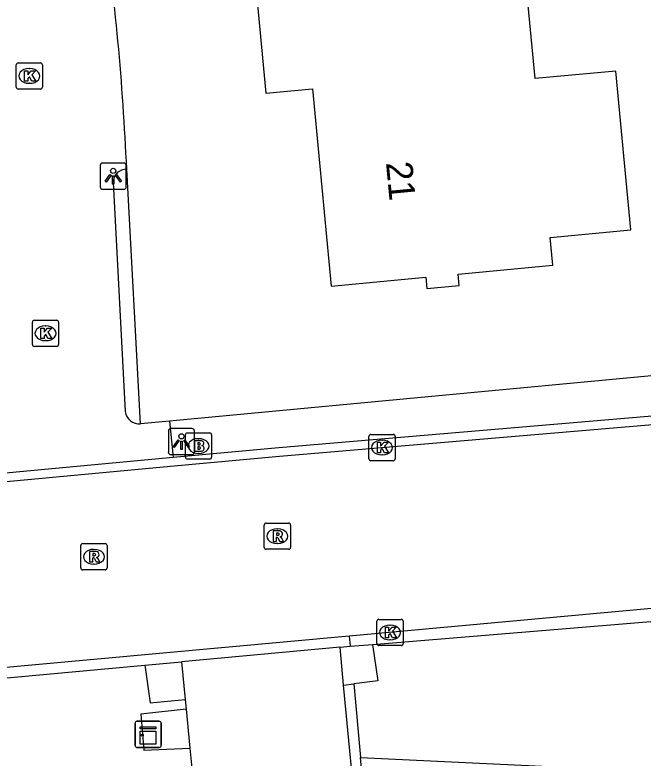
# Model space of a CAD drawing. Extents: x 162157 to 163165, y 378998 to 380775.
# Drawn here: x 162424.68 to 162448.63, y 380633 to 380661.34 of the extents above; entities that cross this region are included whole.
import ezdxf

# ---------------------------------------------------------------- set-up
doc = ezdxf.new("R2010")
doc.units = 0
for name, color, linetype in [('IMGEO_Brandkraan', 7, 'Continuous'), ('IMGEO_Groenvoorziening', 7, 'Continuous'), ('IMGEO_Kast', 7, 'Continuous'), ('IMGEO_Kolk', 7, 'Continuous'), ('IMGEO_Lichtpunt', 7, 'Continuous'), ('IMGEO_Pand', 7, 'Continuous'), ('IMGEO_Pand_nummerreeks', 7, 'Continuous'), ('IMGEO_Rijbaan_lokaal_gesloten', 7, 'Continuous'), ('IMGEO_Rijbaan_lokaal_open', 7, 'Continuous'), ('IMGEO_Rioolput', 7, 'Continuous'), ('IMGEO_Voetpad_open', 7, 'Continuous')]:
    doc.layers.add(name, color=color, linetype=linetype)

msp = doc.modelspace()

# ---------------------------------------------------------------- linework, layer by layer
at = {"layer": 'IMGEO_Brandkraan'}
for p, q in [((162431.253, 380645.401), (162432.105, 380645.401)), ((162431.178, 380644.475), (162431.178, 380645.327)), ((162431.666, 380645.181), (162431.691, 380645.181)), ((162432.179, 380645.327), (162432.179, 380644.475)), ((162431.689, 380644.621), (162431.664, 380644.621)), ((162432.105, 380644.401), (162431.253, 380644.401))]:
    msp.add_line(p, q, dxfattribs=at)
for points in [[(162431.253, 380645.401), (162432.105, 380645.401)], [(162431.178, 380644.475), (162431.178, 380645.327)], [(162431.526, 380645.101), (162431.526, 380644.701), (162431.739, 380644.701)], [(162431.757, 380645.101), (162431.526, 380645.101)], [(162432.179, 380645.327), (162432.179, 380644.475)], [(162431.705, 380645.02), (162431.651, 380645.02), (162431.651, 380644.944)], [(162431.651, 380644.944), (162431.704, 380644.944)], [(162431.713, 380644.868), (162431.651, 380644.868), (162431.651, 380644.787)], [(162431.651, 380644.787), (162431.713, 380644.787)], [(162432.105, 380644.401), (162431.253, 380644.401)]]:
    msp.add_lwpolyline(points, dxfattribs=at)
for centre, radius, start, end in [((162431.255, 380645.325), 0.0765, 91.552, 178.448), ((162431.255, 380645.325), 0.0765, 91.552, 178.448), ((162432.103, 380645.325), 0.0765, 1.552, 88.448), ((162432.103, 380645.325), 0.0765, 1.552, 88.448), ((162431.761, 380644.956), 0.145, 59.4692, 91.5367), ((162431.786, 380645.003), 0.0922, 285.5137, 58.1501), ((162431.706, 380644.982), 0.0379, 267.8285, 90.9355), ((162431.714, 380644.827), 0.0404, 269.8759, 90.5077), ((162431.791, 380644.811), 0.105, 301.3115, 78.989), ((162431.745, 380644.952), 0.251, 268.6676, 293.5347), ((162431.255, 380644.477), 0.0765, 181.552, 268.448), ((162431.255, 380644.477), 0.0765, 181.552, 268.448), ((162432.103, 380644.477), 0.0765, 271.552, 358.448), ((162432.103, 380644.477), 0.0765, 271.552, 358.448)]:
    msp.add_arc(centre, radius, start, end, dxfattribs=at)
for centre, major_axis, ratio, start_param, end_param in [((162431.665, 380644.901), (-0.387, 0.002), 0.722429, 4.712389, 7.853982), ((162431.69, 380644.901), (-0.39, 0.002), 0.717154, 1.570796, 4.712389)]:
    msp.add_ellipse(centre, major_axis=major_axis, ratio=ratio, start_param=start_param, end_param=end_param, dxfattribs=at)
at = {"layer": 'IMGEO_Groenvoorziening'}
msp.add_lwpolyline([(162437.854, 380633.025), (162463.991, 380631.774), (162466.779, 380634.155), (162485.377, 380633.853), (162489.211, 380633.646), (162492.259, 380633.107), (162495.434, 380632.111), (162498.979, 380630.341), (162500, 380629.686), (162501.777, 380628.214), (162507.464, 380626.838)], dxfattribs=at)
at = {"layer": 'IMGEO_Kast'}
for p, q in [((162429.257, 380633.482), (162429.257, 380634.323)), ((162429.257, 380634.323), (162429.257, 380633.482)), ((162429.332, 380634.407), (162430.173, 380634.407)), ((162430.173, 380634.407), (162429.332, 380634.407)), ((162430.257, 380634.332), (162430.257, 380633.491)), ((162430.257, 380633.491), (162430.257, 380634.332)), ((162430.182, 380633.407), (162429.341, 380633.407)), ((162429.341, 380633.407), (162430.182, 380633.407))]:
    msp.add_line(p, q, dxfattribs=at)
for points in [[(162429.452, 380634.197), (162430.052, 380634.197), (162430.052, 380634.112), (162429.452, 380634.112), (162429.452, 380634.197)], [(162429.452, 380634.022), (162430.052, 380634.022), (162430.052, 380633.533), (162429.452, 380633.533), (162429.452, 380634.022)]]:
    msp.add_lwpolyline(points, dxfattribs=at)
msp.add_circle((162429.536, 380633.871), 0.0377, dxfattribs=at)
for centre, start, end in [((162429.335, 380634.329), 92.4484, 184.2845), ((162429.335, 380634.329), 92.4484, 184.2845), ((162430.179, 380634.329), 2.4484, 94.2845), ((162430.179, 380634.329), 2.4484, 94.2845), ((162429.335, 380633.485), 182.4484, 274.2845), ((162429.335, 380633.485), 182.4484, 274.2845), ((162430.179, 380633.485), 272.4484, 4.2845), ((162430.179, 380633.485), 272.4484, 4.2845)]:
    msp.add_arc(centre, 0.0779, start, end, dxfattribs=at)
at = {"layer": 'IMGEO_Kolk'}
for p, q in [((162424.728, 380658.586), (162424.728, 380659.438)), ((162424.803, 380659.512), (162425.655, 380659.512)), ((162425.216, 380659.292), (162425.241, 380659.292)), ((162425.729, 380659.438), (162425.729, 380658.586)), ((162425.239, 380658.732), (162425.214, 380658.732)), ((162425.655, 380658.512), (162424.803, 380658.512)), ((162425.344, 380648.773), (162425.344, 380649.625)), ((162425.419, 380649.699), (162426.271, 380649.699)), ((162426.345, 380649.625), (162426.345, 380648.773)), ((162425.832, 380649.479), (162425.857, 380649.479)), ((162425.855, 380648.919), (162425.83, 380648.919)), ((162426.271, 380648.699), (162425.419, 380648.699)), ((162438.178, 380644.416), (162438.178, 380645.268)), ((162438.253, 380645.342), (162439.105, 380645.342)), ((162438.666, 380645.122), (162438.691, 380645.122)), ((162439.179, 380645.268), (162439.179, 380644.416)), ((162438.689, 380644.562), (162438.664, 380644.562)), ((162439.105, 380644.342), (162438.253, 380644.342)), ((162438.557, 380638.292), (162439.409, 380638.292)), ((162438.482, 380637.366), (162438.482, 380638.218)), ((162438.97, 380638.072), (162438.995, 380638.072)), ((162439.483, 380638.218), (162439.483, 380637.366)), ((162438.993, 380637.512), (162438.968, 380637.512)), ((162439.409, 380637.292), (162438.557, 380637.292))]:
    msp.add_line(p, q, dxfattribs=at)
for points in [[(162424.728, 380658.586), (162424.728, 380659.438)], [(162424.803, 380659.512), (162425.655, 380659.512)], [(162425.729, 380659.438), (162425.729, 380658.586)], [(162425.049, 380659.212), (162425.172, 380659.212), (162425.172, 380659.061), (162425.302, 380659.212), (162425.466, 380659.212), (162425.32, 380659.061), (162425.473, 380658.812), (162425.321, 380658.812), (162425.236, 380658.976), (162425.172, 380658.909), (162425.172, 380658.812), (162425.049, 380658.812), (162425.049, 380659.212)], [(162425.655, 380658.512), (162424.803, 380658.512)], [(162425.344, 380648.773), (162425.344, 380649.625)], [(162425.419, 380649.699), (162426.271, 380649.699)], [(162426.345, 380649.625), (162426.345, 380648.773)], [(162425.665, 380649.399), (162425.788, 380649.399), (162425.788, 380649.248), (162425.918, 380649.399), (162426.082, 380649.399), (162425.936, 380649.248), (162426.089, 380648.999), (162425.937, 380648.999), (162425.852, 380649.163), (162425.788, 380649.096), (162425.788, 380648.999), (162425.665, 380648.999), (162425.665, 380649.399)], [(162426.271, 380648.699), (162425.419, 380648.699)], [(162438.178, 380644.416), (162438.178, 380645.268)], [(162438.253, 380645.342), (162439.105, 380645.342)], [(162439.179, 380645.268), (162439.179, 380644.416)], [(162438.499, 380645.042), (162438.622, 380645.042), (162438.622, 380644.891), (162438.752, 380645.042), (162438.916, 380645.042), (162438.77, 380644.891), (162438.923, 380644.642), (162438.771, 380644.642), (162438.686, 380644.806), (162438.622, 380644.739), (162438.622, 380644.642), (162438.499, 380644.642), (162438.499, 380645.042)], [(162439.105, 380644.342), (162438.253, 380644.342)], [(162438.557, 380638.292), (162439.409, 380638.292)], [(162438.482, 380637.366), (162438.482, 380638.218)], [(162438.803, 380637.992), (162438.926, 380637.992), (162438.926, 380637.841), (162439.056, 380637.992), (162439.22, 380637.992), (162439.074, 380637.841), (162439.227, 380637.592), (162439.075, 380637.592), (162438.99, 380637.756), (162438.926, 380637.689), (162438.926, 380637.592), (162438.803, 380637.592), (162438.803, 380637.992)], [(162439.483, 380638.218), (162439.483, 380637.366)], [(162439.409, 380637.292), (162438.557, 380637.292)]]:
    msp.add_lwpolyline(points, dxfattribs=at)
for centre, start, end in [((162424.805, 380659.436), 91.552, 178.448), ((162424.805, 380659.436), 91.552, 178.448), ((162425.653, 380659.436), 1.552, 88.448), ((162425.653, 380659.436), 1.552, 88.448), ((162424.805, 380658.588), 181.552, 268.448), ((162424.805, 380658.588), 181.552, 268.448), ((162425.653, 380658.588), 271.552, 358.448), ((162425.653, 380658.588), 271.552, 358.448), ((162425.421, 380649.623), 91.552, 178.448), ((162425.421, 380649.623), 91.552, 178.448), ((162426.269, 380649.623), 1.552, 88.448), ((162426.269, 380649.623), 1.552, 88.448), ((162425.421, 380648.775), 181.552, 268.448), ((162425.421, 380648.775), 181.552, 268.448), ((162426.269, 380648.775), 271.552, 358.448), ((162426.269, 380648.775), 271.552, 358.448), ((162438.255, 380645.266), 91.552, 178.448), ((162438.255, 380645.266), 91.552, 178.448), ((162439.103, 380645.266), 1.552, 88.448), ((162439.103, 380645.266), 1.552, 88.448), ((162438.255, 380644.418), 181.552, 268.448), ((162438.255, 380644.418), 181.552, 268.448), ((162439.103, 380644.418), 271.552, 358.448), ((162439.103, 380644.418), 271.552, 358.448), ((162438.559, 380638.216), 91.552, 178.448), ((162438.559, 380638.216), 91.552, 178.448), ((162439.407, 380638.216), 1.552, 88.448), ((162439.407, 380638.216), 1.552, 88.448), ((162438.559, 380637.368), 181.552, 268.448), ((162438.559, 380637.368), 181.552, 268.448), ((162439.407, 380637.368), 271.552, 358.448), ((162439.407, 380637.368), 271.552, 358.448)]:
    msp.add_arc(centre, 0.0765, start, end, dxfattribs=at)
for centre, major_axis, ratio, start_param, end_param in [((162425.215, 380659.012), (-0.387, 0.002), 0.722429, 4.712389, 7.853982), ((162425.24, 380659.012), (-0.39, 0.002), 0.717154, 1.570796, 4.712389), ((162425.831, 380649.199), (-0.387, 0.002), 0.722429, 4.712389, 7.853982), ((162425.856, 380649.199), (-0.39, 0.002), 0.717154, 1.570796, 4.712389), ((162438.665, 380644.842), (-0.387, 0.002), 0.722429, 4.712389, 7.853982), ((162438.69, 380644.842), (-0.39, 0.002), 0.717154, 1.570796, 4.712389), ((162438.969, 380637.792), (-0.387, 0.002), 0.722429, 4.712389, 7.853982), ((162438.994, 380637.792), (-0.39, 0.002), 0.717154, 1.570796, 4.712389)]:
    msp.add_ellipse(centre, major_axis=major_axis, ratio=ratio, start_param=start_param, end_param=end_param, dxfattribs=at)
at = {"layer": 'IMGEO_Lichtpunt'}
for p, q in [((162427.929, 380655.594), (162427.929, 380654.787)), ((162427.929, 380655.594), (162427.929, 380654.787)), ((162428.831, 380655.689), (162428.023, 380655.689)), ((162428.831, 380655.689), (162428.023, 380655.689)), ((162428.925, 380654.787), (162428.925, 380655.594)), ((162428.925, 380654.787), (162428.925, 380655.594)), ((162428.023, 380654.693), (162428.831, 380654.693)), ((162428.023, 380654.693), (162428.831, 380654.693)), ((162430.528, 380645.474), (162430.528, 380644.667)), ((162430.528, 380645.474), (162430.528, 380644.667)), ((162431.43, 380645.569), (162430.622, 380645.569)), ((162431.43, 380645.569), (162430.622, 380645.569)), ((162431.524, 380644.667), (162431.524, 380645.474)), ((162431.524, 380644.667), (162431.524, 380645.474)), ((162430.622, 380644.573), (162431.43, 380644.573)), ((162430.622, 380644.573), (162431.43, 380644.573))]:
    msp.add_line(p, q, dxfattribs=at)
for points in [[(162428.303, 380655.258), (162428.342, 380655.23), (162428.154, 380654.968), (162428.116, 380654.995), (162428.303, 380655.258)], [(162428.405, 380655.21), (162428.452, 380655.21), (162428.452, 380654.888), (162428.405, 380654.888), (162428.405, 380655.21)], [(162428.515, 380655.23), (162428.553, 380655.257), (162428.74, 380654.995), (162428.701, 380654.967), (162428.515, 380655.23)], [(162430.902, 380645.138), (162430.941, 380645.11), (162430.753, 380644.848), (162430.715, 380644.875), (162430.902, 380645.138)], [(162431.004, 380645.09), (162431.051, 380645.09), (162431.051, 380644.768), (162431.004, 380644.768), (162431.004, 380645.09)], [(162431.114, 380645.11), (162431.152, 380645.137), (162431.339, 380644.875), (162431.3, 380644.847), (162431.114, 380645.11)]]:
    msp.add_lwpolyline(points, dxfattribs=at)
for centre in [(162428.428, 380655.392), (162431.027, 380645.272)]:
    msp.add_circle(centre, 0.0994, dxfattribs=at)
for centre, start, end in [((162428.023, 380655.594), 90, 180), ((162428.023, 380655.594), 90, 180), ((162428.831, 380655.594), 0, 90), ((162428.831, 380655.594), 0, 90), ((162428.023, 380654.787), 180, 270), ((162428.023, 380654.787), 180, 270), ((162428.831, 380654.787), 270, 0), ((162428.831, 380654.787), 270, 360), ((162430.622, 380645.474), 90, 180), ((162430.622, 380645.474), 90, 180), ((162431.43, 380645.474), 0, 90), ((162431.43, 380645.474), 0, 90), ((162430.622, 380644.667), 180, 270), ((162430.622, 380644.667), 180, 270), ((162431.43, 380644.667), 270, 0), ((162431.43, 380644.667), 270, 360)]:
    msp.add_arc(centre, 0.0946, start, end, dxfattribs=at)
at = {"layer": 'IMGEO_Pand'}
msp.add_lwpolyline([(162440.383, 380650.906), (162441.618, 380651.023), (162441.577, 380651.451), (162445.184, 380651.792), (162445.083, 380652.857), (162448.16, 380653.148), (162447.588, 380659.201), (162444.511, 380658.91), (162443.783, 380666.619), (162433.563, 380665.652), (162434.245, 380658.352), (162436.029, 380658.523), (162436.739, 380650.994), (162440.343, 380651.335), (162440.383, 380650.906)], dxfattribs=at)
at = {"layer": 'IMGEO_Rijbaan_lokaal_gesloten'}
for points in [[(162462.752, 380647.212), (162434.743, 380644.828), (162430.713, 380644.459)], [(162421.757, 380643.305), (162430.746, 380644.14), (162434.772, 380644.509), (162462.779, 380646.893)], [(162430.713, 380644.459), (162421.728, 380643.624)], [(162465.342, 380640.201), (162437.427, 380637.652)], [(162438.317, 380637.334), (162452.609, 380638.519), (162465.547, 380639.847)], [(162437.427, 380637.652), (162415.859, 380635.682), (162364.95, 380630.872), (162308.18, 380625.53)], [(162437.427, 380637.652), (162437.462, 380637.263)], [(162437.074, 380637.227), (162431.034, 380636.67)], [(162437.074, 380637.227), (162437.462, 380637.263)], [(162437.462, 380637.263), (162438.317, 380637.334)], [(162429.631, 380636.541), (162431.034, 380636.67)], [(162372.405, 380631.16), (162388.242, 380632.742), (162429.631, 380636.541)]]:
    msp.add_lwpolyline(points, dxfattribs=at)
at = {"layer": 'IMGEO_Rijbaan_lokaal_open'}
for points in [[(162428.42, 380654.952), (162428.887, 380646.222)], [(162430.568, 380645.853), (162429.47, 380645.75)], [(162430.568, 380645.853), (162430.713, 380644.459)], [(162437.212, 380635.783), (162437.074, 380637.227)], [(162438.317, 380637.334), (162438.521, 380635.944), (162437.595, 380635.83)], [(162431.034, 380636.67), (162431.172, 380635.238)], [(162429.631, 380636.541), (162429.833, 380635.112), (162431.172, 380635.238)], [(162436.905, 380563.04), (162437.629, 380569.755), (162438.278, 380576.687), (162439.079, 380585.536), (162439.319, 380588.858), (162439.461, 380592.049), (162439.563, 380596.302), (162439.627, 380601.304), (162439.288, 380610.641), (162439.074, 380615.634), (162438.781, 380618.778), (162438.361, 380623.218), (162437.752, 380630.113), (162437.212, 380635.783)], [(162437.212, 380635.783), (162437.595, 380635.83)], [(162437.595, 380635.83), (162437.854, 380633.025)], [(162431.172, 380635.238), (162431.209, 380634.863)], [(162431.209, 380634.863), (162431.352, 380633.378)], [(162431.352, 380633.378), (162431.524, 380631.596)], [(162438.013, 380631.313), (162437.854, 380633.025)]]:
    msp.add_lwpolyline(points, dxfattribs=at)
for centre, radius, start, end in [((162327.094, 380650.947), 101.947, 2.53768, 8.02755), ((162428.941, 380654.94), 0.521, 89.9632, 178.7018), ((162429.411, 380646.274), 0.527, 185.6296, 276.3828)]:
    msp.add_arc(centre, radius, start, end, dxfattribs=at)
at = {"layer": 'IMGEO_Rioolput'}
for p, q in [((162434.262, 380641.963), (162435.114, 380641.963)), ((162434.187, 380641.037), (162434.187, 380641.889)), ((162434.675, 380641.743), (162434.7, 380641.743)), ((162435.188, 380641.889), (162435.188, 380641.037)), ((162427.189, 380640.253), (162427.189, 380641.105)), ((162427.264, 380641.179), (162428.116, 380641.179)), ((162428.19, 380641.105), (162428.19, 380640.253)), ((162434.698, 380641.183), (162434.673, 380641.183)), ((162427.677, 380640.959), (162427.702, 380640.959)), ((162435.114, 380640.963), (162434.262, 380640.963)), ((162427.7, 380640.399), (162427.675, 380640.399)), ((162428.116, 380640.179), (162427.264, 380640.179))]:
    msp.add_line(p, q, dxfattribs=at)
for points in [[(162434.262, 380641.963), (162435.114, 380641.963)], [(162434.187, 380641.037), (162434.187, 380641.889)], [(162435.188, 380641.889), (162435.188, 380641.037)], [(162434.776, 380641.661), (162434.524, 380641.663), (162434.524, 380641.263)], [(162434.524, 380641.263), (162434.648, 380641.263), (162434.648, 380641.425), (162434.659, 380641.425)], [(162434.702, 380641.582), (162434.648, 380641.582), (162434.648, 380641.501)], [(162434.648, 380641.501), (162434.7, 380641.501)], [(162434.706, 380641.396), (162434.777, 380641.263), (162434.917, 380641.263), (162434.852, 380641.389)], [(162427.189, 380640.253), (162427.189, 380641.105)], [(162427.264, 380641.179), (162428.116, 380641.179)], [(162428.19, 380641.105), (162428.19, 380640.253)], [(162427.778, 380640.877), (162427.526, 380640.879), (162427.526, 380640.479)], [(162435.114, 380640.963), (162434.262, 380640.963)], [(162427.526, 380640.479), (162427.65, 380640.479), (162427.65, 380640.641), (162427.661, 380640.641)], [(162427.704, 380640.798), (162427.65, 380640.798), (162427.65, 380640.717)], [(162427.65, 380640.717), (162427.702, 380640.717)], [(162427.708, 380640.612), (162427.779, 380640.479), (162427.919, 380640.479), (162427.854, 380640.605)], [(162428.116, 380640.179), (162427.264, 380640.179)]]:
    msp.add_lwpolyline(points, dxfattribs=at)
for centre, radius, start, end in [((162434.264, 380641.887), 0.0765, 91.552, 178.448), ((162434.264, 380641.887), 0.0765, 91.552, 178.448), ((162435.112, 380641.887), 0.0765, 1.552, 88.448), ((162435.112, 380641.887), 0.0765, 1.552, 88.448), ((162434.658, 380641.372), 0.0533, 26.0293, 88.6989), ((162434.684, 380641.69), 0.19, 274.7715, 282.9687), ((162434.708, 380641.486), 0.0964, 77.0061, 93.1865), ((162434.722, 380641.543), 0.0378, 276.6634, 79.6772), ((162434.775, 380641.551), 0.109, 350.3612, 89.416), ((162434.773, 380641.551), 0.112, 277.5842, 350.9817), ((162434.757, 380641.336), 0.108, 29.5134, 73.7905), ((162427.266, 380641.103), 0.0765, 91.552, 178.448), ((162427.266, 380641.103), 0.0765, 91.552, 178.448), ((162428.114, 380641.103), 0.0765, 1.552, 88.448), ((162428.114, 380641.103), 0.0765, 1.552, 88.448), ((162427.777, 380640.767), 0.109, 350.3612, 89.416), ((162434.264, 380641.039), 0.0765, 181.552, 268.448), ((162434.264, 380641.039), 0.0765, 181.552, 268.448), ((162435.112, 380641.039), 0.0765, 271.552, 358.448), ((162435.112, 380641.039), 0.0765, 271.552, 358.448), ((162427.66, 380640.588), 0.0533, 26.0293, 88.6989), ((162427.686, 380640.906), 0.19, 274.7715, 282.9687), ((162427.71, 380640.702), 0.0964, 77.0061, 93.1865), ((162427.724, 380640.759), 0.0378, 276.6634, 79.6772), ((162427.775, 380640.767), 0.112, 277.5842, 350.9817), ((162427.759, 380640.552), 0.108, 29.5134, 73.7905), ((162427.266, 380640.255), 0.0765, 181.552, 268.448), ((162427.266, 380640.255), 0.0765, 181.552, 268.448), ((162428.114, 380640.255), 0.0765, 271.552, 358.448), ((162428.114, 380640.255), 0.0765, 271.552, 358.448)]:
    msp.add_arc(centre, radius, start, end, dxfattribs=at)
for centre, major_axis, ratio, start_param, end_param in [((162434.674, 380641.463), (-0.387, 0.002), 0.722429, 4.712389, 7.853982), ((162434.699, 380641.463), (-0.39, 0.002), 0.717154, 1.570796, 4.712389), ((162427.676, 380640.679), (-0.387, 0.002), 0.722429, 4.712389, 7.853982), ((162427.701, 380640.679), (-0.39, 0.002), 0.717154, 1.570796, 4.712389)]:
    msp.add_ellipse(centre, major_axis=major_axis, ratio=ratio, start_param=start_param, end_param=end_param, dxfattribs=at)
at = {"layer": 'IMGEO_Voetpad_open'}
for points in [[(162429.47, 380645.75), (162428.941, 380655.461)], [(162458.951, 380648.521), (162430.568, 380645.853)], [(162431.209, 380634.863), (162429.476, 380634.677), (162429.592, 380633.302), (162431.352, 380633.378)]]:
    msp.add_lwpolyline(points, dxfattribs=at)

# ---------------------------------------------------------------- texts
at = {"layer": 'IMGEO_Pand_nummerreeks'}
msp.add_text('21', height=1, rotation=275.3872, dxfattribs=at).set_placement((162438.825, 380655.706))

doc.saveas('drawing.dxf')
